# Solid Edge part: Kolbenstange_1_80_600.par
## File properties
Username: ahadarics
Dokumentum tartalom típus: 0
Author: ahadarics
Last saved by: ahadarics
Revision: 89
Sűrűség: 0,000 kg/m^3
Pontosság: 0,990
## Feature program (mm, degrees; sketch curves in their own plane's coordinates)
base feature "unnamed BaseFeature 1"
thread "unnamed Thread 1"
chamfer "Letörés_1"  SetBackValue2 = 20 deg
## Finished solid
Body 1: solid body, 19 faces, 27 edges, 11 vertices.
  Faces by surface: plane 8, cylinder 5, cone 3, torus 3
  Edges by curve: circle 15, line 7, curve on surface 3, ellipse 2
Bounding box of the edges (mm; curved faces can reach further): 80.000 x 80.000 x 774.000, from (-40, -40, -79.5) to (40, 40, 694.5).
Cylindrical faces by radius (mm): R8.75 x1, R10 x1, R12.25 x1, R12.5 x1, R40 x1
Conical faces (half-angle, radius in mm at the cone's reference point): 20 deg R10 x1, 30 deg R12.375 x1, 60 deg R9.375 x1
Toroidal faces (ring radius, tube radius in mm): R9.15 r0.4 x2, R10.45 r1.8 x1
Planar faces by outward normal: +x 1, +z 3, -x 1, -z 1, oblique 2
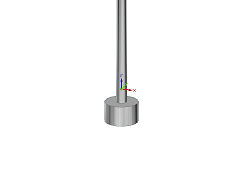
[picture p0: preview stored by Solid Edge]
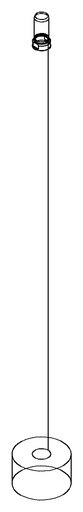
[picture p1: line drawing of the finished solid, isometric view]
